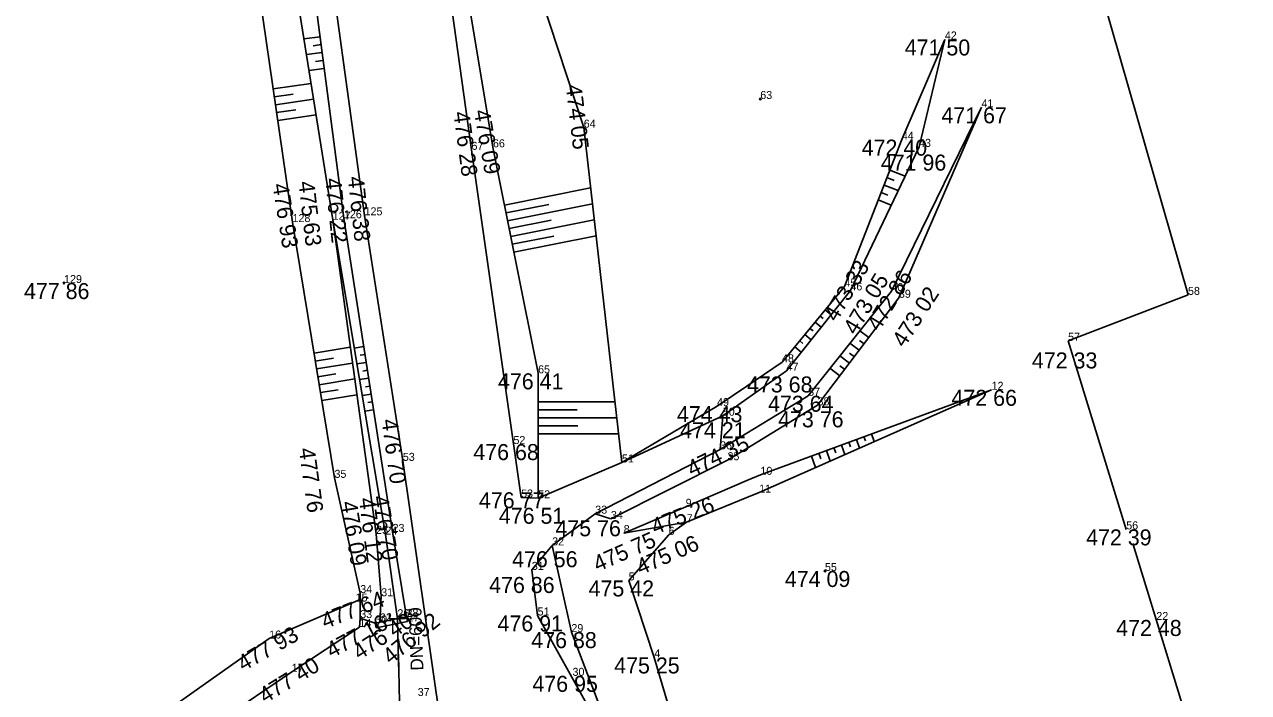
# Model space of a CAD drawing. Extents: x -559180 to -551373, y -1076947 to -1072071.
# Drawn here: x -553795.1 to -553718.7, y -1075795.6 to -1075753.8 of the extents above; entities that cross this region are included whole.
import ezdxf

# ---------------------------------------------------------------- set-up
doc = ezdxf.new("R2010")
doc.units = 0
for name, color, linetype in [('12_PLOTY', 7, 'Continuous'), ('17_KOMUNIKACE', 7, 'Continuous'), ('18_POLOHOPIS', 7, 'Continuous'), ('1_VODA_ZN', 7, 'Continuous'), ('26_SRAFY', 7, 'Continuous'), ('27_HRANA_PATA', 7, 'Continuous'), ('3_BODY', 7, 'Continuous'), ('40_KANAL_ZN', 7, 'Continuous'), ('49_POPIS_KANAL', 7, 'Continuous'), ('6_VYSKY', 7, 'Continuous')]:
    doc.layers.add(name, color=color, linetype=linetype)

# ---------------------------------------------------------------- blocks, each defined once
blk = doc.blocks.new('T')
at = {"layer": '6_VYSKY'}
blk.add_circle((0, 0), 0.05, dxfattribs=at)
blk = doc.blocks.new('VYUST')
at = {"layer": '40_KANAL_ZN'}
for p, q in [((-0.35, 0.5), (0, 0.5)), ((0, 0.5), (0, -0.5)), ((0, 0), (3, 0.001)), ((-0.35, -0.5), (0, -0.5))]:
    blk.add_line(p, q, dxfattribs=at)
blk = doc.blocks.new('JS600')
at = {"layer": '49_POPIS_KANAL'}
blk.add_text('DN=600', height=0.8, rotation=0.00002, dxfattribs=at).set_placement((0.752, -0.172))
blk = doc.blocks.new('POINT_DISPLAY')
blk.add_line((0, 0), (0, 0))

msp = doc.modelspace()

# ---------------------------------------------------------------- linework, layer by layer
at = {"layer": '12_PLOTY'}
for p, q in [((-553722.44, -1075770.73), (-553727.72, -1075752.3)), ((-553729.93, -1075773.6), (-553722.44, -1075770.73)), ((-553726.3, -1075785.38), (-553729.93, -1075773.6)), ((-553718.66, -1075809.85), (-553725.883, -1075786.26))]:
    msp.add_line(p, q, dxfattribs=at)
at = {"layer": '17_KOMUNIKACE'}
for p, q in [((-553767.2, -1075761.67), (-553769.72, -1075743.59)), ((-553773.88, -1075765.76), (-553776.53, -1075746.5)), ((-553764.1, -1075783.39), (-553767.2, -1075761.67)), ((-553771.49, -1075781.1), (-553773.88, -1075765.76)), ((-553751.5, -1075778.28), (-553757.8, -1075781.2)), ((-553751.67, -1075780.38), (-553751.5, -1075778.28)), ((-553759.47, -1075784.4), (-553751.67, -1075780.38)), ((-553771.49, -1075781.1), (-553767.99, -1075805.4)), ((-553757.8, -1075781.2), (-553763.03, -1075783.44)), ((-553763.03, -1075783.44), (-553764.1, -1075783.39)), ((-553762.16, -1075786.38), (-553759.47, -1075784.4)), ((-553763.43, -1075787.91), (-553762.16, -1075786.38)), ((-553763.07, -1075790.76), (-553763.43, -1075787.91)), ((-553759.5, -1075797.19), (-553763.07, -1075790.76))]:
    msp.add_line(p, q, dxfattribs=at)
at = {"layer": '18_POLOHOPIS'}
for p, q in [((-553771.26, -1075790.85), (-553773.21, -1075791.25)), ((-553771.2, -1075791.13), (-553771.26, -1075790.85)), ((-553773.15, -1075791.53), (-553773.21, -1075791.25)), ((-553771.2, -1075791.13), (-553773.15, -1075791.53))]:
    msp.add_line(p, q, dxfattribs=at)
at = {"layer": '26_SRAFY'}
for p, q in [((-553777.667, -1075754.73), (-553776.659, -1075754.598)), ((-553777.51, -1075755.718), (-553776.529, -1075755.589)), ((-553777.091, -1075755.159), (-553776.594, -1075755.093)), ((-553776.948, -1075756.149), (-553776.464, -1075756.085)), ((-553777.353, -1075756.706), (-553776.399, -1075756.581)), ((-553777.225, -1075757.514), (-553779.59, -1075757.858)), ((-553778.332, -1075758.18), (-553779.518, -1075758.352)), ((-553777.068, -1075758.501), (-553779.446, -1075758.847)), ((-553778.182, -1075759.169), (-553779.374, -1075759.342)), ((-553776.911, -1075759.489), (-553779.302, -1075759.837)), ((-553740.114, -1075763.307), (-553741.063, -1075762.936)), ((-553759.76, -1075764.044), (-553765.139, -1075765.118)), ((-553740.546, -1075764.211), (-553741.427, -1075763.868)), ((-553740.788, -1075763.581), (-553741.245, -1075763.402)), ((-553740.979, -1075765.116), (-553741.79, -1075764.8)), ((-553741.186, -1075764.499), (-553741.608, -1075764.334)), ((-553762.372, -1075765.076), (-553765.041, -1075765.609)), ((-553759.646, -1075765.041), (-553764.943, -1075766.099)), ((-553762.217, -1075766.064), (-553764.846, -1075766.589)), ((-553759.532, -1075766.038), (-553764.748, -1075767.08)), ((-553762.062, -1075767.053), (-553764.65, -1075767.57)), ((-553759.418, -1075767.035), (-553764.552, -1075768.06)), ((-553744.736, -1075771.968), (-553745.101, -1075771.667)), ((-553745.358, -1075772.751), (-553745.737, -1075772.438)), ((-553745.233, -1075772.206), (-553745.419, -1075772.053)), ((-553745.981, -1075773.534), (-553746.374, -1075773.21)), ((-553745.863, -1075772.983), (-553746.055, -1075772.824)), ((-553742.941, -1075772.969), (-553742.378, -1075773.394)), ((-553774.771, -1075773.999), (-553777.037, -1075774.371)), ((-553774.53, -1075774.053), (-553773.926, -1075773.959)), ((-553746.603, -1075774.317), (-553747.01, -1075773.982)), ((-553746.492, -1075773.76), (-553746.692, -1075773.596)), ((-553743.564, -1075773.752), (-553742.981, -1075774.192)), ((-553742.966, -1075773.577), (-553742.68, -1075773.793)), ((-553775.829, -1075774.679), (-553776.956, -1075774.864)), ((-553774.148, -1075774.499), (-553773.85, -1075774.453)), ((-553744.186, -1075774.535), (-553743.584, -1075774.99)), ((-553743.579, -1075774.367), (-553743.283, -1075774.591)), ((-553774.634, -1075774.99), (-553776.875, -1075775.358)), ((-553774.365, -1075775.039), (-553773.773, -1075774.947)), ((-553773.989, -1075775.487), (-553773.696, -1075775.441)), ((-553744.809, -1075775.318), (-553744.187, -1075775.788)), ((-553744.192, -1075775.158), (-553743.886, -1075775.389)), ((-553775.68, -1075775.668), (-553776.794, -1075775.851)), ((-553774.497, -1075775.981), (-553776.713, -1075776.345)), ((-553774.2, -1075776.025), (-553773.62, -1075775.935)), ((-553775.531, -1075776.657), (-553776.633, -1075776.838)), ((-553774.36, -1075776.972), (-553776.552, -1075777.331)), ((-553774.035, -1075777.012), (-553773.466, -1075776.923)), ((-553773.83, -1075776.474), (-553773.543, -1075776.429)), ((-553773.87, -1075777.998), (-553773.313, -1075777.912)), ((-553773.671, -1075777.461), (-553773.39, -1075777.418)), ((-553758.233, -1075777.406), (-553763.038, -1075777.412)), ((-553760.607, -1075777.909), (-553763.037, -1075777.912)), ((-553758.119, -1075778.406), (-553763.036, -1075778.412)), ((-553760.549, -1075778.909), (-553763.036, -1075778.912)), ((-553758.005, -1075779.406), (-553763.035, -1075779.412)), ((-553742.039, -1075779.9), (-553742.216, -1075779.42)), ((-553743.872, -1075780.711), (-553744.093, -1075780.11)), ((-553743.518, -1075780.223), (-553743.623, -1075779.938)), ((-553742.955, -1075780.305), (-553743.154, -1075779.765)), ((-553742.591, -1075779.848), (-553742.685, -1075779.593)), ((-553745.705, -1075781.521), (-553745.97, -1075780.801)), ((-553745.373, -1075780.973), (-553745.5, -1075780.628)), ((-553744.788, -1075781.116), (-553745.031, -1075780.455)), ((-553744.446, -1075780.598), (-553744.562, -1075780.283))]:
    msp.add_line(p, q, dxfattribs=at)
at = {"layer": '27_HRANA_PATA'}
for p, q in [((-553765.86, -1075761.51), (-553768.87, -1075743.42)), ((-553760.19, -1075760.28), (-553765.86, -1075743.01)), ((-553778.38, -1075766.18), (-553781.15, -1075747.13)), ((-553775.87, -1075766.04), (-553778.95, -1075746.66)), ((-553775.17, -1075765.94), (-553777.7, -1075746.67)), ((-553737.63, -1075754.77), (-553740.32, -1075761.03)), ((-553737.63, -1075754.77), (-553739.24, -1075761.48)), ((-553740.97, -1075770.49), (-553735.34, -1075759.01)), ((-553740.5, -1075770.91), (-553735.34, -1075759.01)), ((-553757.8, -1075781.2), (-553760.19, -1075760.28)), ((-553740.32, -1075761.03), (-553743.9, -1075770.21)), ((-553763.04, -1075775.63), (-553765.86, -1075761.51)), ((-553739.24, -1075761.48), (-553743.53, -1075770.45)), ((-553775.76, -1075782.16), (-553778.38, -1075766.18)), ((-553773.16, -1075785.66), (-553775.87, -1075766.04)), ((-553772.58, -1075785.71), (-553775.87, -1075766.04)), ((-553775.17, -1075765.94), (-553772.13, -1075785.54)), ((-553743.9, -1075770.21), (-553747.8, -1075774.94)), ((-553743.53, -1075770.45), (-553747.52, -1075775.47)), ((-553746.17, -1075777.03), (-553740.97, -1075770.49)), ((-553745.58, -1075777.63), (-553740.5, -1075770.91)), ((-553763.03, -1075783.44), (-553763.04, -1075775.63)), ((-553747.8, -1075774.94), (-553750, -1075776.425)), ((-553747.52, -1075775.47), (-553750, -1075777.221)), ((-553750, -1075776.425), (-553751.86, -1075777.68)), ((-553750, -1075779.363), (-553746.17, -1075777.03)), ((-553749.23, -1075783.08), (-553734.71, -1075776.66)), ((-553749.15, -1075781.97), (-553734.71, -1075776.66)), ((-553751.86, -1075777.68), (-553757.8, -1075781.2)), ((-553750, -1075777.221), (-553751.5, -1075778.28)), ((-553750, -1075780.323), (-553745.58, -1075777.63)), ((-553751.67, -1075780.38), (-553750, -1075779.363)), ((-553751.21, -1075781.06), (-553750, -1075780.323)), ((-553758.49, -1075784.73), (-553751.21, -1075781.06)), ((-553774.15, -1075789.36), (-553775.76, -1075782.16)), ((-553753.82, -1075783.97), (-553750, -1075782.334)), ((-553750, -1075782.334), (-553749.15, -1075781.97)), ((-553750, -1075783.394), (-553749.23, -1075783.08)), ((-553757.69, -1075785.61), (-553753.82, -1075783.97)), ((-553753.76, -1075784.93), (-553750, -1075783.394)), ((-553759.47, -1075784.4), (-553758.49, -1075784.73)), ((-553772.13, -1075785.54), (-553771.26, -1075790.85)), ((-553753.76, -1075784.93), (-553757.69, -1075785.61)), ((-553754.88, -1075785.72), (-553753.76, -1075784.93)), ((-553773.16, -1075785.66), (-553772.84, -1075789.56)), ((-553772.58, -1075785.71), (-553771.816, -1075790.964)), ((-553757.38, -1075788.57), (-553754.88, -1075785.72)), ((-553760.96, -1075791.8), (-553762.16, -1075786.38)), ((-553755.78, -1075793.38), (-553757.38, -1075788.57)), ((-553774.15, -1075790.92), (-553774.15, -1075789.36)), ((-553774.15, -1075789.766), (-553779.84, -1075792.2)), ((-553772.84, -1075789.56), (-553772.923, -1075791.191)), ((-553774.2, -1075791.48), (-553774.15, -1075790.92)), ((-553773.21, -1075791.25), (-553774.15, -1075790.92)), ((-553774.2, -1075791.48), (-553778.43, -1075794.28)), ((-553779.84, -1075792.2), (-553792.28, -1075800.97)), ((-553758.118, -1075799.249), (-553760.96, -1075791.8)), ((-553750.4, -1075811.72), (-553755.78, -1075793.38)), ((-553778.43, -1075794.28), (-553791.08, -1075802.87))]:
    msp.add_line(p, q, dxfattribs=at)

# ---------------------------------------------------------------- block references
at = {"layer": '1_VODA_ZN'}
for p in [(-553737.63, -1075754.77), (-553749.16, -1075758.49), (-553735.34, -1075759.01), (-553760.19, -1075760.28), (-553740.32, -1075761.03), (-553767.2, -1075761.67), (-553765.86, -1075761.51), (-553739.24, -1075761.48), (-553778.38, -1075766.18), (-553775.87, -1075766.04), (-553775.17, -1075765.94), (-553773.88, -1075765.76), (-553792.65, -1075769.99), (-553743.9, -1075770.21), (-553743.53, -1075770.45), (-553740.97, -1075770.49), (-553740.5, -1075770.91), (-553722.44, -1075770.73), (-553729.93, -1075773.6), (-553763.04, -1075775.63), (-553747.8, -1075774.94), (-553747.52, -1075775.47), (-553746.17, -1075777.03), (-553734.71, -1075776.66), (-553751.86, -1075777.68), (-553745.58, -1075777.63), (-553751.5, -1075778.28), (-553764.58, -1075780.05), (-553751.67, -1075780.38), (-553771.49, -1075781.1), (-553757.8, -1075781.2), (-553751.21, -1075781.06), (-553775.76, -1075782.16), (-553749.15, -1075781.97), (-553749.23, -1075783.08), (-553764.1, -1075783.39), (-553763.03, -1075783.44), (-553753.82, -1075783.97), (-553759.47, -1075784.4), (-553758.49, -1075784.73), (-553772.13, -1075785.54), (-553753.76, -1075784.93), (-553726.3, -1075785.38), (-553773.16, -1075785.66), (-553772.58, -1075785.71), (-553757.69, -1075785.61), (-553754.88, -1075785.72), (-553762.16, -1075786.38), (-553763.43, -1075787.91), (-553757.38, -1075788.57), (-553745.12, -1075787.98), (-553774.15, -1075789.36), (-553774.44, -1075789.89), (-553772.84, -1075789.56), (-553774.15, -1075790.92), (-553771.83, -1075790.87), (-553771.26, -1075790.85), (-553763.07, -1075790.76), (-553774.2, -1075791.48), (-553773.21, -1075791.25), (-553772.92, -1075791.13), (-553771.2, -1075791.13), (-553724.42, -1075791.04), (-553779.84, -1075792.2), (-553760.96, -1075791.8), (-553755.78, -1075793.38), (-553778.43, -1075794.28)]:
    msp.add_blockref('POINT_DISPLAY', p, dxfattribs=at)
at = {"layer": '40_KANAL_ZN'}
for p, xscale, yscale, rotation in [((-553771.816, -1075790.964), 1.0000020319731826, 1.0000020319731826, -88.75819614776), ((-553771.703, -1075796.177), 1.0000021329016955, 1.0000021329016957, 91.24207059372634)]:
    msp.add_blockref('VYUST', p, dxfattribs=dict(at, xscale=xscale, yscale=yscale, rotation=rotation))
at = {"layer": '49_POPIS_KANAL', "xscale": 1.000001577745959, "yscale": 1.000001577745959, "rotation": 91.95765720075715}
msp.add_blockref('JS600', (-553770.346, -1075794.948), dxfattribs=at)
at = {"layer": '6_VYSKY'}
for p in [(-553749.16, -1075758.49), (-553749.16, -1075758.49), (-553792.65, -1075769.99), (-553792.65, -1075769.99), (-553745.12, -1075787.98), (-553745.12, -1075787.98)]:
    msp.add_blockref('T', p, dxfattribs=at)

# ---------------------------------------------------------------- texts
at = {"layer": '3_BODY'}
for s, p in [('42', (-553737.63, -1075754.77)), ('63', (-553749.16, -1075758.49)), ('41', (-553735.34, -1075759.01)), ('64', (-553760.19, -1075760.28)), ('66', (-553765.86, -1075761.51)), ('44', (-553740.32, -1075761.03)), ('43', (-553739.24, -1075761.48)), ('67', (-553767.2, -1075761.67)), ('128', (-553778.38, -1075766.18)), ('127', (-553775.87, -1075766.04)), ('126', (-553775.17, -1075765.94)), ('125', (-553773.88, -1075765.76)), ('129', (-553792.65, -1075769.99)), ('45', (-553743.9, -1075770.21)), ('46', (-553743.53, -1075770.45)), ('40', (-553740.97, -1075770.49)), ('58', (-553722.44, -1075770.73)), ('39', (-553740.5, -1075770.91)), ('57', (-553729.93, -1075773.6)), ('48', (-553747.8, -1075774.94)), ('65', (-553763.04, -1075775.63)), ('47', (-553747.52, -1075775.47)), ('12', (-553734.71, -1075776.66)), ('37', (-553746.17, -1075777.03)), ('38', (-553745.58, -1075777.63)), ('49', (-553751.86, -1075777.68)), ('50', (-553751.5, -1075778.28)), ('52', (-553764.58, -1075780.05)), ('36', (-553751.67, -1075780.38)), ('53', (-553771.49, -1075781.1)), ('51', (-553757.8, -1075781.2)), ('35', (-553751.21, -1075781.06)), ('35', (-553775.76, -1075782.16)), ('10', (-553749.15, -1075781.97)), ('53', (-553764.1, -1075783.39)), ('52', (-553763.03, -1075783.44)), ('11', (-553749.23, -1075783.08)), ('33', (-553759.47, -1075784.4)), ('9', (-553753.82, -1075783.97)), ('34', (-553758.49, -1075784.73)), ('7', (-553753.76, -1075784.93)), ('25', (-553773.16, -1075785.66)), ('24', (-553772.58, -1075785.71)), ('23', (-553772.13, -1075785.54)), ('8', (-553757.69, -1075785.61)), ('6', (-553754.88, -1075785.72)), ('56', (-553726.3, -1075785.38)), ('32', (-553762.16, -1075786.38)), ('31', (-553763.43, -1075787.91)), ('55', (-553745.12, -1075787.98)), ('5', (-553757.38, -1075788.57)), ('15', (-553774.44, -1075789.89)), ('34', (-553774.15, -1075789.36)), ('31', (-553772.84, -1075789.56)), ('33', (-553774.15, -1075790.92)), ('30', (-553773.21, -1075791.25)), ('32', (-553772.92, -1075791.13)), ('26', (-553771.83, -1075790.87)), ('28', (-553771.26, -1075790.85)), ('27', (-553771.2, -1075791.13)), ('51', (-553763.07, -1075790.76)), ('22', (-553724.42, -1075791.04)), ('14', (-553774.2, -1075791.48)), ('29', (-553760.96, -1075791.8)), ('16', (-553779.84, -1075792.2)), ('4', (-553755.78, -1075793.38)), ('17', (-553778.43, -1075794.28)), ('30', (-553760.89, -1075794.53)), ('37', (-553770.56, -1075795.79))]:
    msp.add_text(s, height=0.5, dxfattribs=at).set_placement(p)
at = {"layer": '6_VYSKY'}
for s, p in [('471 50', (-553740.135, -1075755.77)), ('471 67', (-553737.845, -1075760.01)), ('472 40', (-553742.825, -1075762.03)), ('471 96', (-553741.633, -1075762.966)), ('477 86', (-553795.155, -1075770.99)), ('472 33', (-553732.194, -1075775.324)), ('476 41', (-553765.545, -1075776.63)), ('473 68', (-553749.988, -1075776.826)), ('473 64', (-553748.675, -1075778.03)), ('472 66', (-553737.215, -1075777.66)), ('474 43', (-553754.365, -1075778.68)), ('474 21', (-553754.167, -1075779.684)), ('473 76', (-553748.047, -1075779.004)), ('476 68', (-553767.085, -1075781.05)), ('476 77', (-553766.736, -1075784.062)), ('476 51', (-553765.491, -1075785.031)), ('475 76', (-553761.958, -1075785.812)), ('472 39', (-553728.805, -1075786.38)), ('476 56', (-553764.665, -1075787.744)), ('476 86', (-553766.097, -1075789.355)), ('475 42', (-553759.885, -1075789.57)), ('474 09', (-553747.625, -1075788.98)), ('476 91', (-553765.575, -1075791.76)), ('472 48', (-553726.925, -1075792.04)), ('476 88', (-553763.465, -1075792.8)), ('475 25', (-553758.285, -1075794.38)), ('476 95', (-553763.395, -1075795.53))]:
    msp.add_text(s, height=1, dxfattribs=at).set_placement(p)
for s, rotation, p in [('474 05', 276.69265, (-553761.321, -1075757.634)), ('476 28', 277.53012, (-553768.332, -1075759.332)), ('476 09', 279.83043, (-553767.053, -1075759.234)), ('476 38', 276.09662, (-553774.929, -1075763.372)), ('476 93', 278.99523, (-553779.635, -1075763.835)), ('475 63', 276.59538, (-553778.018, -1075763.674)), ('476 22', 275.84256, (-553776.344, -1075763.468)), ('473 33', 59.25421, (-553744.393, -1075772.468)), ('473 05', 59.26188, (-553743.184, -1075773.287)), ('473 05', 59.26188, (-553743.184, -1075773.287)), ('472 86', 58.75923, (-553741.739, -1075773.066)), ('473 02', 57.12462, (-553740.159, -1075774.071)), ('476 70', 277.81398, (-553772.821, -1075778.544)), ('474 35', 25.50487, (-553753.434, -1075782.102)), ('477 76', 277.89264, (-553777.988, -1075780.344)), ('476 09', 279.14534, (-553775.357, -1075783.688)), ('476 12', 277.30213, (-553774.239, -1075783.453)), ('476 70', 279.44212, (-553773.399, -1075783.344)), ('475 26', 21.48036, (-553755.733, -1075785.721)), ('475 75', 23.72668, (-553759.324, -1075788.047)), ('475 06', 23.53479, (-553756.639, -1075788.244)), ('477 64', 21.27104, (-553776.347, -1075791.612)), ('477 16', 27.97948, (-553775.94, -1075793.449)), ('476 40', 32.70582, (-553774.204, -1075793.569)), ('476 92', 39.12933, (-553772.247, -1075793.856)), ('477 93', 29.71207, (-553781.455, -1075794.274)), ('477 40', 31.5192, (-553780.083, -1075796.281))]:
    msp.add_text(s, height=1, rotation=rotation, dxfattribs=at).set_placement(p)

doc.saveas('drawing.dxf')
